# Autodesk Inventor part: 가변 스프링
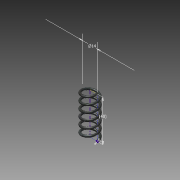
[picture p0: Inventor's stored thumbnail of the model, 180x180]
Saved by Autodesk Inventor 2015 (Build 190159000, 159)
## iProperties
Created: 2020-02
Part Number: 가변 스프링
Material: 강철
Document SubType Name: Modeling
Designer: LINEART-A501
Density: 7.85 g/cm^3
Appearance: 플레이트
Mass: 6.50802 g
Surface Area: 16.7391 cm^2
Volume: 0.829047 cm^3
Author: LINEART-A501
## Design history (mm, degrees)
sketch "스케치1"
  geometry: L1 (0, 0)-(7, 0); L2 (7, 0)-(7, 35.5); L3 (7, 35.5)-(0, 35.5); L4 (0, 35.5)-(0, 0); C1 r 1 at (7, 0)
  constraints: 8 end point, 2 parallel, 1 centre point, 1 coincident, 1 horizontal, 1 perpendicular
  dimensions: "d0" = 14 diameter of L2 L4; "d1" = 35.5 distance of L1.end L2.end (derived); "d2" = 2 diameter of C1
feature "코일1" pitch "d3" = 10; turns "d5" = 6; dims "d4" = 35.5 (= d1), "d6" = 0, angle "d7" = 90 deg, angle "d8" = 90 deg, "d9" = 0, "d10" = 0
node "솔리드1"
